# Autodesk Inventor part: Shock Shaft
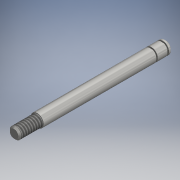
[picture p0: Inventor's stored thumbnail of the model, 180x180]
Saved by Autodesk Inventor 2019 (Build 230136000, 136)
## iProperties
Shininess: 60.0
Compacted: True
Length Units: 11272
Angle Units: 11279
Time Units: 11290
Mass Units: 11286
Length Display Precision: 4
Angle Display Precision: 2
Company: Autodesk
Created: 2000-03
Part Number: Shock Shaft
Project: Inventor Samples
User Status: IN PROGRESS
Document SubType Name: Modeling
Designer: Autodesk, Inc.
Density: 8.08 g/cm^3
Mass: 2.29313 g
Surface Area: 3.90959 cm^2
Volume: 0.283804 cm^3
Material: Stainless Steel
Appearance: Steel
Density: 0.0
Volumn: 0.0
Area: 0.0
PropertySet Name: Model Information
Control State: 0
Master: False
Checked Out: False
Checked Out Date: 2018-05-30
Last Check In Date: 2018-05-30
Author: Autodesk, Inc.
Revision Number: A
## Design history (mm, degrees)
node "Extrusion1" dims "d0" = 31.75, "d1" = 0
  sketch "Sketch2"
    geometry: C1 r 1.587 at (-3.459, -7.697)
    constraints: 1 centre point
    dimensions: "d3" = 3.175 diameter of C1
node "Extrusion2" dims "d4" = 5.715, "d5" = 0
  sketch "Sketch3"
    geometry: C1 r 1.587 at (0, 0) reference; C2 r 1.422 at (0, 0)
    constraints: 1 centre point, 1 coincident
    dimensions: "d2" = 2.8448 diameter of C2
workplane "Work Plane1"
node "Extrusion3" dims "d8" = 0.381, "d9" = 0
  sketch "Sketch4"
    geometry: C1 r 1.587 at (0, 0) reference; C2 r 1.191 at (0, 0)
    constraints: 1 centre point, 1 coincident
    dimensions: "d7" = 2.38125 diameter of C2
workplane "Work Plane2"
node "Extrusion4" dims "d11" = 0.381 (= d8), "d12" = 0
  sketch "Sketch5"
    geometry: C1 r 1.587 at (0, 0) reference; C2 r 1.191 at (0, 0) reference
node "Chamfer1" dims "d13" = 0.381, "d14" = 0.381, "d17" = 45 deg
thread "Thread1" dims "d15" = 25.4, "d16" = 0
body "Solid1"
other parameters: "d6" = -0.8128, "d10" = -2.38125
